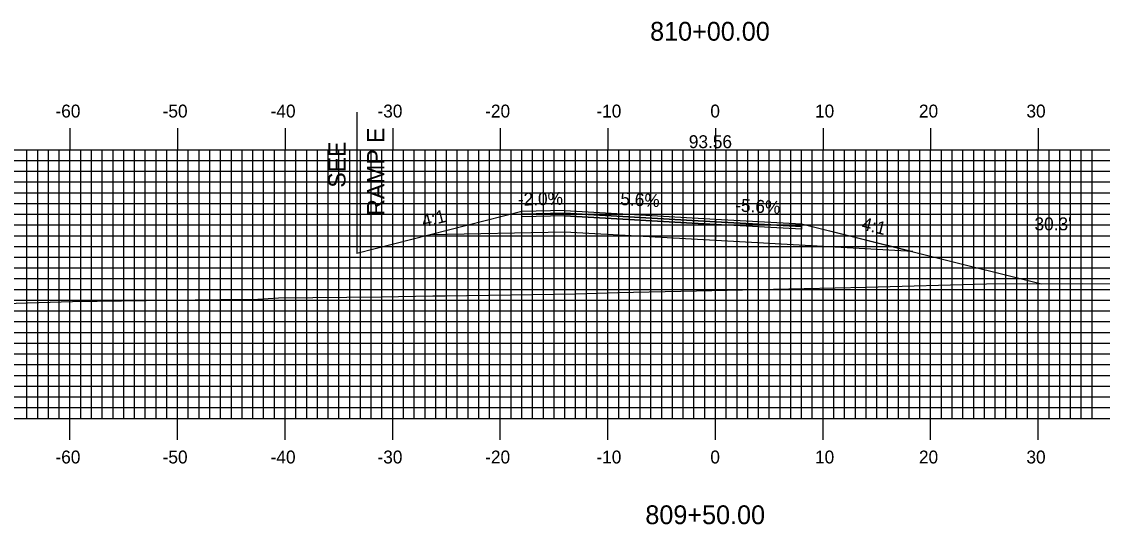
# Model space of a CAD drawing. Extents: x 1666 to 2009, y -1658 to -1438.
# Drawn here: x 1767.2 to 1867.6, y -1599.5 to -1552.7 of the extents above; entities that cross this region are included whole.
import ezdxf

# ---------------------------------------------------------------- set-up
doc = ezdxf.new("R2010")
doc.units = 0
for name, color, linetype in [('ANNOTATION', 7, 'Continuous'), ('D_Roadway_Centerline_Text', 7, 'Continuous'), ('D_Roadway_Edge_Shoulder', 7, 'Continuous'), ('D_Roadway_Edge_TW', 7, 'Continuous'), ('D_Roadway_Pavement', 7, 'Continuous'), ('D_Roadway_SlopeLines', 7, 'Continuous'), ('D_Roadway_SubGrade', 7, 'Continuous'), ('D_Text_Standard', 7, 'Continuous'), ('H_V ANNOTATION', 7, 'Continuous'), ('MAJOR', 7, 'Continuous'), ('MINOR', 7, 'Continuous'), ('S_Roadway_Centerline', 7, 'Continuous')]:
    doc.layers.add(name, color=color, linetype=linetype)

msp = doc.modelspace()

# ---------------------------------------------------------------- linework, layer by layer
at = {"layer": 'ANNOTATION'}
for p, q in [((1813.67, -1570.34), (1798.34, -1574.25)), ((1817.67, -1570.26), (1813.67, -1570.34)), ((1817.67, -1570.51), (1813.67, -1570.59)), ((1817.67, -1572.26), (1805.17, -1572.51)), ((1805.33, -1572.5), (1805.17, -1572.51))]:
    msp.add_line(p, q, dxfattribs=at)
msp.add_lwpolyline([(1817.67, -1570.76), (1813.67, -1570.84), (1813.67, -1570.34)], dxfattribs=at)
at = {"layer": 'D_Roadway_Edge_Shoulder'}
for points in [[(1831.67, -1571.05), (1839.67, -1571.5), (1839.67, -1571.75), (1831.67, -1571.3)], [(1831.67, -1571.3), (1839.67, -1571.75), (1839.67, -1572), (1831.67, -1571.55)]]:
    msp.add_lwpolyline(points, close=True, dxfattribs=at)
at = {"layer": 'D_Roadway_Edge_TW'}
msp.add_lwpolyline([(1817.67, -1570.26), (1831.67, -1571.05), (1831.67, -1571.3), (1817.67, -1570.51)], close=True, dxfattribs=at)
at = {"layer": 'D_Roadway_Pavement'}
msp.add_lwpolyline([(1817.67, -1570.51), (1831.67, -1571.3), (1831.67, -1571.55), (1817.67, -1570.76)], close=True, dxfattribs=at)
msp.add_lwpolyline([(1831.67, -1571.3), (1831.67, -1571.55)], dxfattribs=at)
msp.add_lwpolyline([(1831.67, -1571.3), (1831.67, -1571.55)], dxfattribs=at)
at = {"layer": 'D_Roadway_SlopeLines'}
msp.add_lwpolyline([(1839.67, -1571.5), (1851.67, -1574.5), (1861.97, -1577.07)], dxfattribs=at)
at = {"layer": 'D_Roadway_SubGrade'}
msp.add_line((1798.34, -1561.11), (1798.34, -1574.25), dxfattribs=at)
for points in [[(1817.67, -1570.76), (1831.67, -1571.55), (1831.67, -1573.05), (1817.67, -1572.26)], [(1831.67, -1571.55), (1831.67, -1571.3), (1839.67, -1571.75), (1839.67, -1571.5), (1850, -1574.08), (1831.67, -1573.05)]]:
    msp.add_lwpolyline(points, close=True, dxfattribs=at)
at = {"layer": 'MAJOR'}
for p, q in [((1771.67, -1562.6), (1771.67, -1564.6)), ((1781.67, -1562.6), (1781.67, -1564.6)), ((1791.67, -1562.6), (1791.67, -1564.6)), ((1801.67, -1562.6), (1801.67, -1564.6)), ((1811.67, -1562.6), (1811.67, -1564.6)), ((1821.67, -1562.6), (1821.67, -1564.6)), ((1831.67, -1562.6), (1831.67, -1564.6)), ((1841.67, -1562.6), (1841.67, -1564.6)), ((1851.67, -1562.6), (1851.67, -1564.6)), ((1861.67, -1562.6), (1861.67, -1564.6)), ((1691.67, -1564.6), (1971.67, -1564.6)), ((1691.67, -1564.6), (1971.67, -1564.6)), ((1771.67, -1589.6), (1771.67, -1564.6)), ((1781.67, -1589.6), (1781.67, -1564.6)), ((1791.67, -1589.6), (1791.67, -1564.6)), ((1801.67, -1589.6), (1801.67, -1564.6)), ((1811.67, -1589.6), (1811.67, -1564.6)), ((1821.67, -1589.6), (1821.67, -1564.6)), ((1831.67, -1589.6), (1831.67, -1564.6)), ((1841.67, -1589.6), (1841.67, -1564.6)), ((1851.67, -1589.6), (1851.67, -1564.6)), ((1861.67, -1589.6), (1861.67, -1564.6)), ((1691.67, -1569.6), (1971.67, -1569.6)), ((1691.67, -1574.6), (1971.67, -1574.6)), ((1691.67, -1579.6), (1971.67, -1579.6)), ((1691.67, -1584.6), (1971.67, -1584.6)), ((1691.67, -1589.6), (1971.67, -1589.6)), ((1691.67, -1589.6), (1971.67, -1589.6)), ((1771.67, -1591.61), (1771.67, -1589.6)), ((1781.67, -1591.61), (1781.67, -1589.6)), ((1791.67, -1591.61), (1791.67, -1589.6)), ((1801.67, -1591.61), (1801.67, -1589.6)), ((1811.67, -1591.61), (1811.67, -1589.6)), ((1821.67, -1591.61), (1821.67, -1589.6)), ((1831.67, -1591.61), (1831.67, -1589.6)), ((1841.67, -1591.61), (1841.67, -1589.6)), ((1851.67, -1591.61), (1851.67, -1589.6)), ((1861.67, -1591.61), (1861.67, -1589.6))]:
    msp.add_line(p, q, dxfattribs=at)
at = {"layer": 'MINOR'}
for p, q in [((1767.67, -1589.6), (1767.67, -1564.6)), ((1768.67, -1589.6), (1768.67, -1564.6)), ((1769.67, -1589.6), (1769.67, -1564.6)), ((1770.67, -1589.6), (1770.67, -1564.6)), ((1772.67, -1589.6), (1772.67, -1564.6)), ((1773.67, -1589.6), (1773.67, -1564.6)), ((1774.67, -1589.6), (1774.67, -1564.6)), ((1775.67, -1589.6), (1775.67, -1564.6)), ((1776.67, -1589.6), (1776.67, -1564.6)), ((1777.67, -1589.6), (1777.67, -1564.6)), ((1778.67, -1589.6), (1778.67, -1564.6)), ((1779.67, -1589.6), (1779.67, -1564.6)), ((1780.67, -1589.6), (1780.67, -1564.6)), ((1782.67, -1589.6), (1782.67, -1564.6)), ((1783.67, -1589.6), (1783.67, -1564.6)), ((1784.67, -1589.6), (1784.67, -1564.6)), ((1785.67, -1589.6), (1785.67, -1564.6)), ((1786.67, -1589.6), (1786.67, -1564.6)), ((1787.67, -1589.6), (1787.67, -1564.6)), ((1788.67, -1589.6), (1788.67, -1564.6)), ((1789.67, -1589.6), (1789.67, -1564.6)), ((1790.67, -1589.6), (1790.67, -1564.6)), ((1792.67, -1589.6), (1792.67, -1564.6)), ((1793.67, -1589.6), (1793.67, -1564.6)), ((1794.67, -1589.6), (1794.67, -1564.6)), ((1795.67, -1589.6), (1795.67, -1564.6)), ((1796.67, -1589.6), (1796.67, -1564.6)), ((1797.67, -1589.6), (1797.67, -1564.6)), ((1798.67, -1589.6), (1798.67, -1564.6)), ((1799.67, -1589.6), (1799.67, -1564.6)), ((1800.67, -1589.6), (1800.67, -1564.6)), ((1802.67, -1589.6), (1802.67, -1564.6)), ((1803.67, -1589.6), (1803.67, -1564.6)), ((1804.67, -1589.6), (1804.67, -1564.6)), ((1805.67, -1589.6), (1805.67, -1564.6)), ((1806.67, -1589.6), (1806.67, -1564.6)), ((1807.67, -1589.6), (1807.67, -1564.6)), ((1808.67, -1589.6), (1808.67, -1564.6)), ((1809.67, -1589.6), (1809.67, -1564.6)), ((1810.67, -1589.6), (1810.67, -1564.6)), ((1812.67, -1589.6), (1812.67, -1564.6)), ((1813.67, -1589.6), (1813.67, -1564.6)), ((1814.67, -1589.6), (1814.67, -1564.6)), ((1815.67, -1589.6), (1815.67, -1564.6)), ((1816.67, -1589.6), (1816.67, -1564.6)), ((1817.67, -1589.6), (1817.67, -1564.6)), ((1818.67, -1589.6), (1818.67, -1564.6)), ((1819.67, -1589.6), (1819.67, -1564.6)), ((1820.67, -1589.6), (1820.67, -1564.6)), ((1822.67, -1589.6), (1822.67, -1564.6)), ((1823.67, -1589.6), (1823.67, -1564.6)), ((1824.67, -1589.6), (1824.67, -1564.6)), ((1825.67, -1589.6), (1825.67, -1564.6)), ((1826.67, -1589.6), (1826.67, -1564.6)), ((1827.67, -1589.6), (1827.67, -1564.6)), ((1828.67, -1589.6), (1828.67, -1564.6)), ((1829.67, -1589.6), (1829.67, -1564.6)), ((1830.67, -1589.6), (1830.67, -1564.6)), ((1832.67, -1589.6), (1832.67, -1564.6)), ((1833.67, -1589.6), (1833.67, -1564.6)), ((1834.67, -1589.6), (1834.67, -1564.6)), ((1835.67, -1589.6), (1835.67, -1564.6)), ((1836.67, -1589.6), (1836.67, -1564.6)), ((1837.67, -1589.6), (1837.67, -1564.6)), ((1838.67, -1589.6), (1838.67, -1564.6)), ((1839.67, -1589.6), (1839.67, -1564.6)), ((1840.67, -1589.6), (1840.67, -1564.6)), ((1842.67, -1589.6), (1842.67, -1564.6)), ((1843.67, -1589.6), (1843.67, -1564.6)), ((1844.67, -1589.6), (1844.67, -1564.6)), ((1845.67, -1589.6), (1845.67, -1564.6)), ((1846.67, -1589.6), (1846.67, -1564.6)), ((1847.67, -1589.6), (1847.67, -1564.6)), ((1848.67, -1589.6), (1848.67, -1564.6)), ((1849.67, -1589.6), (1849.67, -1564.6)), ((1850.67, -1589.6), (1850.67, -1564.6)), ((1852.67, -1589.6), (1852.67, -1564.6)), ((1853.67, -1589.6), (1853.67, -1564.6)), ((1854.67, -1589.6), (1854.67, -1564.6)), ((1855.67, -1589.6), (1855.67, -1564.6)), ((1856.67, -1589.6), (1856.67, -1564.6)), ((1857.67, -1589.6), (1857.67, -1564.6)), ((1858.67, -1589.6), (1858.67, -1564.6)), ((1859.67, -1589.6), (1859.67, -1564.6)), ((1860.67, -1589.6), (1860.67, -1564.6)), ((1862.67, -1589.6), (1862.67, -1564.6)), ((1863.67, -1589.6), (1863.67, -1564.6)), ((1864.67, -1589.6), (1864.67, -1564.6)), ((1865.67, -1589.6), (1865.67, -1564.6)), ((1866.67, -1589.6), (1866.67, -1564.6)), ((1691.67, -1565.6), (1971.67, -1565.6)), ((1691.67, -1566.6), (1971.67, -1566.6)), ((1691.67, -1567.6), (1971.67, -1567.6)), ((1691.67, -1568.6), (1971.67, -1568.6)), ((1691.67, -1570.6), (1971.67, -1570.6)), ((1691.67, -1571.6), (1971.67, -1571.6)), ((1691.67, -1572.6), (1971.67, -1572.6)), ((1691.67, -1573.6), (1971.67, -1573.6)), ((1691.67, -1575.6), (1971.67, -1575.6)), ((1691.67, -1576.6), (1971.67, -1576.6)), ((1691.67, -1577.6), (1971.67, -1577.6)), ((1691.67, -1578.6), (1971.67, -1578.6)), ((1691.67, -1580.6), (1971.67, -1580.6)), ((1691.67, -1581.6), (1971.67, -1581.6)), ((1691.67, -1582.6), (1971.67, -1582.6)), ((1691.67, -1583.6), (1971.67, -1583.6)), ((1691.67, -1585.6), (1971.67, -1585.6)), ((1691.67, -1586.6), (1971.67, -1586.6)), ((1691.67, -1587.6), (1971.67, -1587.6)), ((1691.67, -1588.6), (1971.67, -1588.6))]:
    msp.add_line(p, q, dxfattribs=at)
at = {"layer": 'S_Roadway_Centerline'}
msp.add_lwpolyline([(1764.57, -1578.93), (1771.9, -1578.74), (1785.59, -1578.54), (1789.13, -1578.51), (1791.05, -1578.37), (1800.6, -1578.28), (1805.4, -1578.2), (1806.55, -1578.2), (1818.66, -1578.02), (1822.58, -1577.88), (1829.89, -1577.72), (1839.9, -1577.51), (1845.69, -1577.4), (1856.87, -1577.09), (1865.74, -1577.06), (1871.37, -1577.09)], dxfattribs=at)

# ---------------------------------------------------------------- texts
at = {"layer": 'ANNOTATION'}
for s, height, rotation, p in [('RAMP E', 1.6, 90, (1800.88, -1570.74)), ('SEE', 1.6, 90, (1797.28, -1568.13)), ('-2.0%', 1.2, 1.1458, (1813.31, -1569.81)), ('5.6%', 1.2, 356.779, (1822.8, -1569.74)), ('-5.6%', 1.2, 356.7791, (1833.48, -1570.34)), ('4:1', 1.2, 14.0362, (1804.54, -1571.84)), ('4:1', 1.2, 345.9638, (1845.18, -1572.01))]:
    msp.add_text(s, height=height, rotation=rotation, dxfattribs=at).set_placement(p)
at = {"layer": 'D_Roadway_Centerline_Text'}
msp.add_text('93.56', height=1.2, dxfattribs=at).set_placement((1829.19, -1564.45))
at = {"layer": 'D_Text_Standard'}
msp.add_text("30.3'", height=1.2, dxfattribs=at).set_placement((1861.32, -1572.1))
at = {"layer": 'H_V ANNOTATION'}
for s, height, p in [('810+00.00', 1.75, (1825.59, -1554.45)), ('-60', 1.2, (1770.32, -1561.6)), ('-50', 1.2, (1780.28, -1561.6)), ('-40', 1.2, (1790.32, -1561.6)), ('-30', 1.2, (1800.25, -1561.6)), ('-20', 1.2, (1810.26, -1561.6)), ('-10', 1.2, (1820.6, -1561.6)), ('0', 1.2, (1831.19, -1561.6)), ('10', 1.2, (1840.92, -1561.6)), ('20', 1.2, (1850.58, -1561.6)), ('30', 1.2, (1860.57, -1561.6)), ('-60', 1.2, (1770.32, -1593.8)), ('-50', 1.2, (1780.28, -1593.8)), ('-40', 1.2, (1790.32, -1593.8)), ('-30', 1.2, (1800.25, -1593.8)), ('-20', 1.2, (1810.26, -1593.8)), ('-10', 1.2, (1820.6, -1593.8)), ('0', 1.2, (1831.19, -1593.8)), ('10', 1.2, (1840.92, -1593.8)), ('20', 1.2, (1850.58, -1593.8)), ('30', 1.2, (1860.57, -1593.8)), ('809+50.00', 1.75, (1825.15, -1599.45))]:
    msp.add_text(s, height=height, dxfattribs=at).set_placement(p)

doc.saveas('drawing.dxf')
